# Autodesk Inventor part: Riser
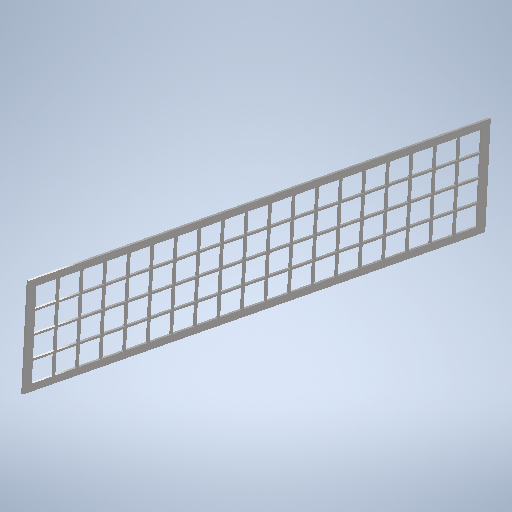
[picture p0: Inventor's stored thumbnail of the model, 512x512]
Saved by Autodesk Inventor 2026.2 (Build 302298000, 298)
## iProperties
RuleStatus: InUse
Created: 2022-06
Part Number: Riser
Material: Steel, Galvanized
Document SubType Name: Modeling
Designer: reaumed
Density: 7.85 g/cm^3
Appearance: Galvanized
Mass: 845.798 g
Surface Area: 1112.5 cm^2
Volume: 107.745 cm^3
AfterAnyParamChange0: pattern base location
AfterAnyUserParamChange0: pattern base location
Author: reaumed
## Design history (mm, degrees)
workplane "Work Plane1"
sketch "Sketch1"
  geometry: L1 (-342.9, -222.25)-(342.9, -222.25); L2 (342.9, -222.25)-(342.9, -381); L3 (342.9, -381)-(-342.9, -381); L4 (-342.9, -381)-(-342.9, -222.25); 3 further points
  constraints: 8 end point, 2 parallel, 1 coincident, 1 horizontal, 1 midpoint, 1 perpendicular
  dimensions: "ActualRiserWidth" = 685.8 distance of L2.end L3.end (= Width - 2 x StringerThickness); "ActualRiserHeight" = 158.75 distance of L1.end L2.end (= Rise - TreadThickness); "d5" = 222.25 distance from line of L1 point (0, 0) (= Rise + TreadThickness); "d6" = 0 horizontal distance of point (0, 0) point (0, -222.25)
extrude "Extrusion1" new body sketch "Sketch1" distance "d3" = 3.175 (= RiserThickness); taper "d4" = 0 deg
sketch "Sketch2"
  geometry: L1 (233.362, -330.2)-(265.112, -330.2); L2 (265.112, -330.2)-(265.112, -298.45); L3 (265.112, -298.45)-(233.362, -298.45); L4 (233.362, -298.45)-(233.362, -330.2); L5 (233.362, -330.2)-(265.112, -298.45); L6 (381, -342.9)-(381, 342.9) reference; L7 (381, 342.9)-(222.25, 342.9) reference; L8 (381, -342.9)-(222.25, 342.9); 3 further points
  constraints: 12 end point, 2 midpoint, 2 parallel, 1 horizontal, 1 perpendicular
  dimensions: "d7" = 31.75 distance of L2.end L3.end (= HoleSize); "HoleSize" = 31.75 distance of L3.end L1.start; "x_loc" = 314.325 vertical distance of point (249.237, -314.325) point (0, 0); "y_loc" = 52.3875 horizontal distance of point (301.625, 0) point (249.237, -314.325)
extrude "Grating Extrusion" cut sketch "Sketch2" extent not by distance; stored distance "d12" = 0; taper "d13" = 0 deg
body "Solid1"
pattern_linear "Grating Pattern" dims "d16" = 34.925 (= HoleSize + HoleSpacing), "d19" = 34.925 (= HoleSize + HoleSpacing)
other parameters: "Run" = 228.6 [user parameter; used in 1 equation term], "Width" = 762 [user parameter; used in 1 equation term], "Rise" = 190.5 [user parameter; used in 2 equation terms], "TreadThickness" = 31.75 [user parameter; used in 2 equation terms], "RiserThickness" = 3.175 [user parameter; used in 1 equation term], "d0" = 228.6 (= Run), "StringerThickness" = 38.1 [user parameter; used in 1 equation term], "HoleSpacing" = 3.175 [user parameter; used in 2 equation terms]
